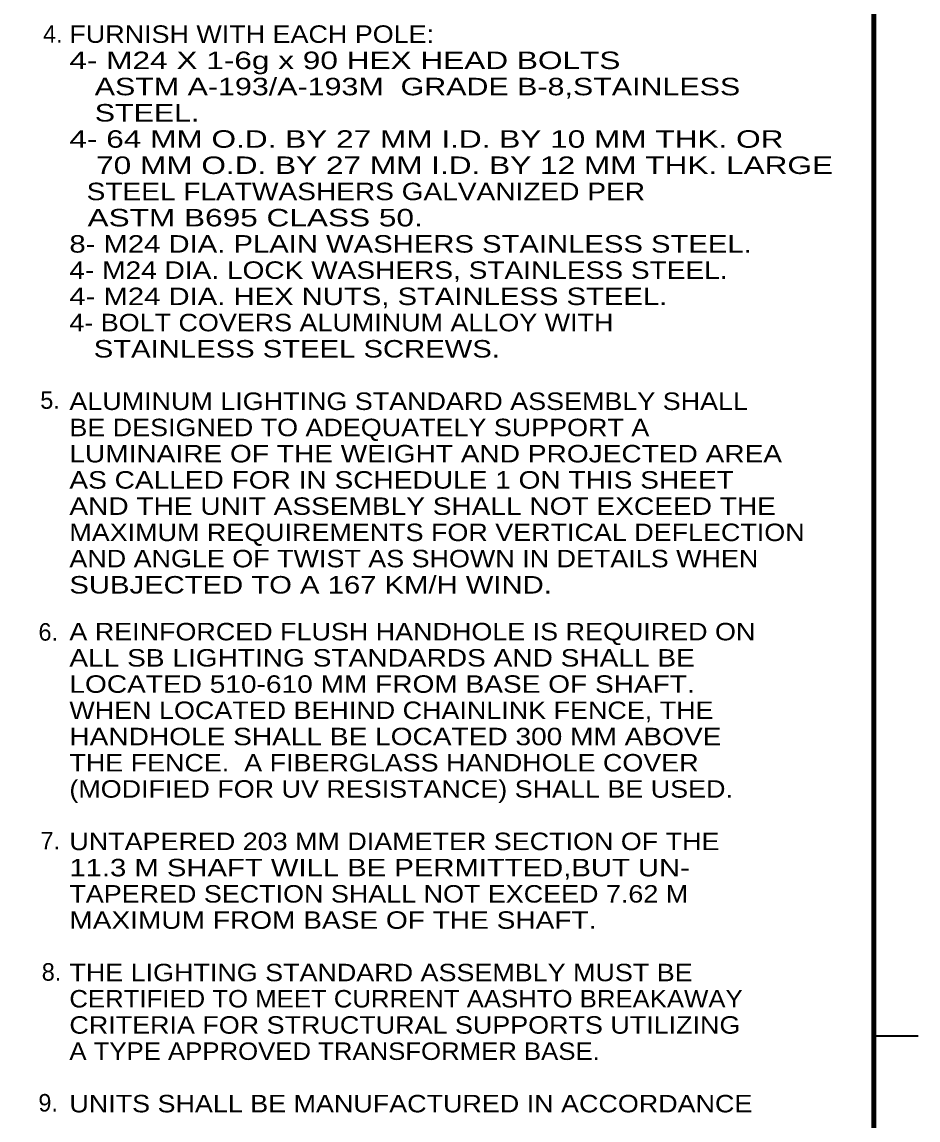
# Model space of a CAD drawing. Extents: x 312583 to 312854, y 144418 to 144597.
# Drawn here: x 312811.99 to 312850.92, y 144500.43 to 144548.17 of the extents above; entities that cross this region are included whole.
import ezdxf
from ezdxf.enums import TextEntityAlignment as Align

# ---------------------------------------------------------------- set-up
doc = ezdxf.new("R2010")
doc.units = 0
doc.header["$LTSCALE"] = 0.3
doc.layers.add('1', color=7, linetype='Continuous', lineweight=35)
doc.layers.add('2', color=7, linetype='Continuous')

msp = doc.modelspace()

# ---------------------------------------------------------------- linework, layer by layer
at = {"layer": '1'}
msp.add_line((312849, 144504.0846), (312850.92, 144504.0846), dxfattribs=at)
at = {"layer": '1', "lineweight": 158}
msp.add_lwpolyline([(312849, 144423.0846), (312849, 144585.0846), (312616.5, 144585.0846), (312616.5, 144423.0846)], close=True, dxfattribs=at)

# ---------------------------------------------------------------- texts
at = {"layer": '2'}
for s, p in [('4.', (312813.3252, 144547.2646)), ('5.', (312813.2048, 144531.349)), ('6.', (312813.1278, 144521.2705)), ('7.', (312813.2176, 144512.1948)), ('8.', (312813.2683, 144506.4885)), ('9.', (312813.1225, 144500.8012))]:
    msp.add_text(s, height=0.76, dxfattribs=at).set_placement(p, align=Align.CENTER)
for s, width, p in [('FURNISH WITH EACH POLE:  ', 1.15, (312814.0451, 144547.2583)), ('4- M24 X 1-6g x 90 HEX HEAD BOLTS  ', 1.35, (312814.0451, 144546.1183)), ('   ASTM A-193/A-193M  GRADE B-8,STAINLESS  ', 1.3, (312814.0451, 144544.9783)), ('   STEEL.  ', 1.3, (312814.0451, 144543.8383)), ('4- 64 MM O.D. BY 27 MM I.D. BY 10 MM THK. OR   ', 1.35, (312814.0451, 144542.6983)), ('  70 MM O.D. BY 27 MM I.D. BY 12 MM THK. LARGE ', 1.35, (312814.4442, 144541.5583)), ('   STEEL FLATWASHERS GALVANIZED PER ', 1.2, (312813.7791, 144540.4183)), ('   ASTM B695 CLASS 50.  ', 1.35, (312813.6904, 144539.2783)), ('8- M24 DIA. PLAIN WASHERS STAINLESS STEEL.  ', 1.25, (312814.0451, 144538.1383)), ('4- M24 DIA. LOCK WASHERS, STAINLESS STEEL.  ', 1.2, (312814.0451, 144536.9983)), ('4- M24 DIA. HEX NUTS, STAINLESS STEEL.', 1.25, (312814.0451, 144535.8583)), ('4- BOLT COVERS ALUMINUM ALLOY WITH', 1.15, (312814.0451, 144534.7183)), ('   STAINLESS STEEL SCREWS. ', 1.25, (312814.0451, 144533.5783)), ('ALUMINUM LIGHTING STANDARD ASSEMBLY SHALL  ', 1.15, (312814.0451, 144531.2983)), ('BE DESIGNED TO ADEQUATELY SUPPORT A  ', 1.15, (312814.0451, 144530.1583)), ('LUMINAIRE OF THE WEIGHT AND PROJECTED AREA    ', 1.2, (312814.0451, 144529.0183)), ('AS CALLED FOR IN SCHEDULE 1 ON THIS SHEET  ', 1.2, (312814.0451, 144527.8783)), ('AND THE UNIT ASSEMBLY SHALL NOT EXCEED THE  ', 1.2, (312814.0451, 144526.7383)), ('MAXIMUM REQUIREMENTS FOR VERTICAL DEFLECTION  ', 1.15, (312814.0451, 144525.5983)), ('AND ANGLE OF TWIST AS SHOWN IN DETAILS WHEN', 1.15, (312814.0451, 144524.4583)), ('SUBJECTED TO A 167 KM/H WIND.  ', 1.25, (312814.0451, 144523.3183)), ('A REINFORCED FLUSH HANDHOLE IS REQUIRED ON  ', 1.15, (312814.0451, 144521.2831)), ('ALL SB LIGHTING STANDARDS AND SHALL BE  ', 1.2, (312814.0451, 144520.1431)), ('LOCATED 510-610 MM FROM BASE OF SHAFT.  ', 1.2, (312814.0451, 144519.0031)), ('WHEN LOCATED BEHIND CHAINLINK FENCE, THE  ', 1.15, (312814.0451, 144517.8631)), ('HANDHOLE SHALL BE LOCATED 300 MM ABOVE   ', 1.2, (312814.0451, 144516.7231)), ('THE FENCE.  A FIBERGLASS HANDHOLE COVER', 1.15, (312814.0451, 144515.5831)), ('(MODIFIED FOR UV RESISTANCE) SHALL BE USED.', 1.15, (312814.0451, 144514.4431)), ('UNTAPERED 203 MM DIAMETER SECTION OF THE ', 1.15, (312814.0451, 144512.1631)), ('11.3 M SHAFT WILL BE PERMITTED,BUT UN-  ', 1.25, (312814.0451, 144511.0231)), ('TAPERED SECTION SHALL NOT EXCEED 7.62 M', 1.15, (312814.0451, 144509.8831)), ('MAXIMUM FROM BASE OF THE SHAFT.    ', 1.2, (312814.0451, 144508.7431)), ('THE LIGHTING STANDARD ASSEMBLY MUST BE  ', 1.15, (312814.0451, 144506.4631)), ('CERTIFIED TO MEET CURRENT AASHTO BREAKAWAY', 1.1, (312814.0451, 144505.3231)), ('CRITERIA FOR STRUCTURAL SUPPORTS UTILIZING ', 1.15, (312814.0451, 144504.1831)), ('A TYPE APPROVED TRANSFORMER BASE.', 1.1, (312814.0451, 144503.0431)), ('UNITS SHALL BE MANUFACTURED IN ACCORDANCE ', 1.15, (312814.0451, 144500.7631))]:
    msp.add_text(s, height=0.76, dxfattribs=dict(at, width=width)).set_placement(p)

doc.saveas('drawing.dxf')
